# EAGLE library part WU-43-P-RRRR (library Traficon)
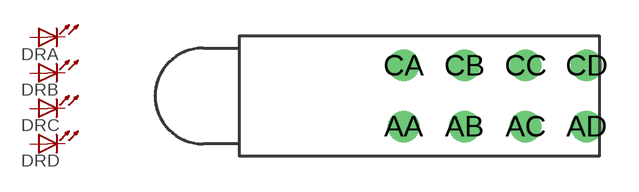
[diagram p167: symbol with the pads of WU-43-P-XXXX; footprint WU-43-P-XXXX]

Designator prefix DR; gates A=LED-2 B=LED-2 C=LED-2 D=LED-2

## WU-43-P-RRRR  [WU-43-P-XXXX]
AA  A:A  pas
AB  B:A  pas
AC  C:A  pas
AD  D:A  pas
CA  A:C  pas
CB  B:C  pas
CC  C:C  pas
CD  D:C  pas

## Footprint WU-43-P-XXXX (pad centres in mm)
drill 0.8 round: AA -0.66,-1.27; AB 1.88,-1.27; AC 4.42,-1.27; AD 6.96,-1.27; CA -0.66,1.27; CB 1.88,1.27; CC 4.42,1.27; CD 6.96,1.27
